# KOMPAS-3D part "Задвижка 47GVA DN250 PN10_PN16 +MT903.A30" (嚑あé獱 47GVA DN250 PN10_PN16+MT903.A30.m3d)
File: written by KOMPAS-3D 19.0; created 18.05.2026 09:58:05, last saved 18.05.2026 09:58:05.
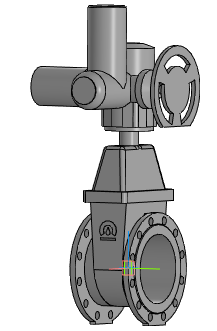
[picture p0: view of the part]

Document properties: Автор: Энергия; Полное имя файла: ..\Задвижка 47GVA DN50_DN1000+MT903.A\Задвижка 47GVA DN250 PN10_PN16+MT903.A30.a3d

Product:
- Part/product: Задвижка 47GVA DN250 PN10_PN16 +MT903.A30
    Масса: 309.749
  - Body: Электропривод МТ903.А30 без блока управления
      Масса: 163.268
  - Body: Задвижка 47GVA DN250 PN10_PN16 без исполнит. мех.
      Масса: 146.481

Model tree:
1. Операция без истории:1
2. Операция без истории:2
